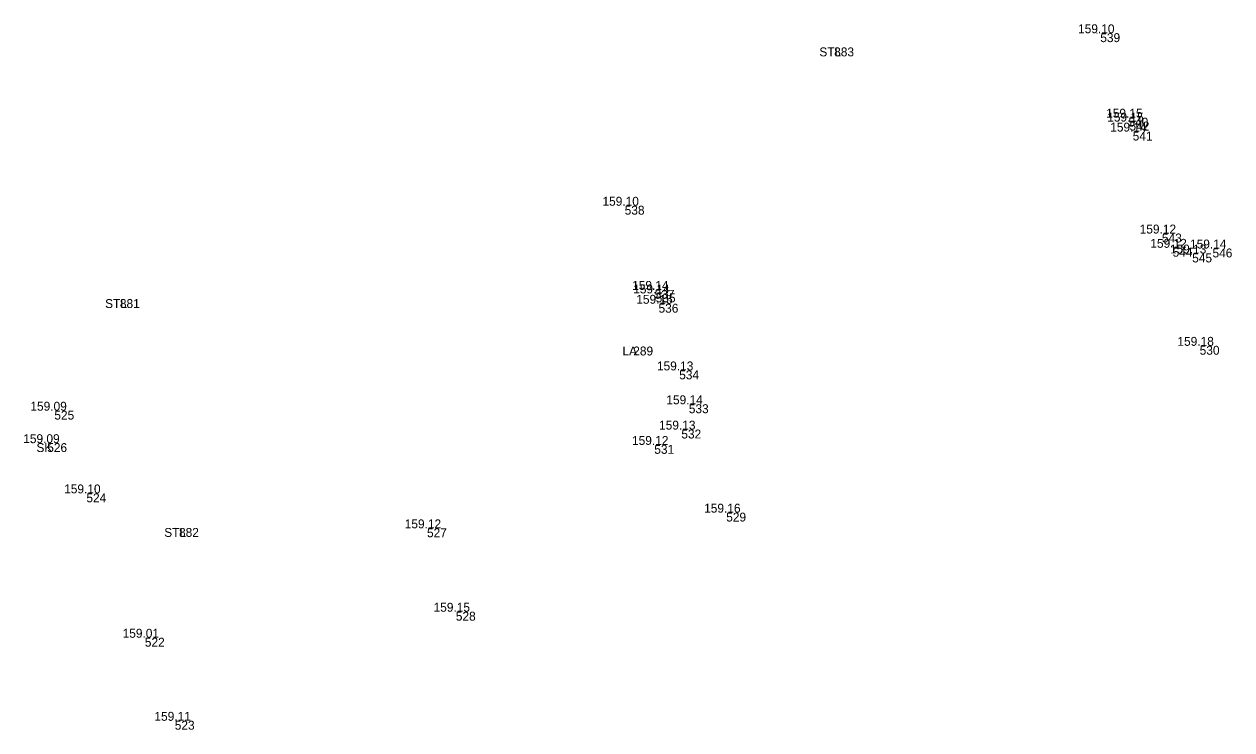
# Model space of a CAD drawing. Extents: x -583198 to -582878, y -1211024 to -1210637.
# Drawn here: x -583031.76 to -582997.86, y -1210873.42 to -1210853.63 of the extents above; entities that cross this region are included whole.
import ezdxf

# ---------------------------------------------------------------- set-up
doc = ezdxf.new("R2010")
doc.units = 0
for name, color, linetype in [('1   Kódy', 7, 'Continuous'), ('4   Body podrobné', 7, 'Continuous'), ('5   Body podrobné - čísla', 7, 'Continuous'), ('6   Body podrobné - výšky', 7, 'Continuous')]:
    doc.layers.add(name, color=color, linetype=linetype)

msp = doc.modelspace()

# ---------------------------------------------------------------- linework, layer by layer
at = {"layer": '4   Body podrobné'}
for p, q in [((-583001.65, -1210853.88), (-583001.649, -1210853.88)), ((-583009.12, -1210854.28), (-583009.119, -1210854.28)), ((-583000.86, -1210856.25), (-583000.859, -1210856.25)), ((-583000.83, -1210856.36), (-583000.829, -1210856.36)), ((-583000.74, -1210856.64), (-583000.739, -1210856.64)), ((-583015, -1210858.72), (-583014.999, -1210858.72)), ((-582999.92, -1210859.5), (-582999.919, -1210859.5)), ((-582999.62, -1210859.9), (-582999.619, -1210859.9)), ((-582999.07, -1210860.06), (-582999.069, -1210860.06)), ((-582998.5, -1210859.92), (-582998.499, -1210859.92)), ((-583014.16, -1210861.08), (-583014.159, -1210861.08)), ((-583014.13, -1210861.18), (-583014.129, -1210861.18)), ((-583029.17, -1210861.34), (-583029.169, -1210861.34)), ((-583014.05, -1210861.47), (-583014.049, -1210861.47)), ((-583014.76, -1210862.67), (-583014.759, -1210862.67)), ((-582998.86, -1210862.65), (-582998.859, -1210862.65)), ((-583013.47, -1210863.34), (-583013.469, -1210863.34)), ((-583013.2, -1210864.29), (-583013.199, -1210864.29)), ((-583031.01, -1210864.47), (-583031.009, -1210864.47)), ((-583013.41, -1210865), (-583013.409, -1210865)), ((-583031.21, -1210865.38), (-583031.209, -1210865.38)), ((-583014.17, -1210865.43), (-583014.169, -1210865.43)), ((-583030.11, -1210866.79), (-583030.109, -1210866.79)), ((-583012.15, -1210867.33), (-583012.149, -1210867.33)), ((-583027.51, -1210867.76), (-583027.509, -1210867.76)), ((-583020.55, -1210867.77), (-583020.549, -1210867.77)), ((-583019.74, -1210870.11), (-583019.739, -1210870.11)), ((-583028.47, -1210870.84), (-583028.469, -1210870.84)), ((-583027.63, -1210873.17), (-583027.629, -1210873.17))]:
    msp.add_line(p, q, dxfattribs=at)

# ---------------------------------------------------------------- texts
at = {"layer": '1   Kódy'}
for s, p in [('STL', (-583009.442, -1210854.53)), ('STL', (-583029.492, -1210861.59)), ('LA', (-583014.97, -1210862.92)), ('SK', (-583031.419, -1210865.63)), ('STL', (-583027.832, -1210868.01))]:
    msp.add_text(s, height=0.25, dxfattribs=at).set_placement(p)
at = {"layer": '5   Body podrobné - čísla'}
for s, p in [(' 539', (-583001.65, -1210854.13)), (' 883', (-583009.12, -1210854.53)), (' 540', (-583000.86, -1210856.5)), (' 542', (-583000.83, -1210856.61)), (' 541', (-583000.74, -1210856.89)), (' 538', (-583015, -1210858.97)), (' 543', (-582999.92, -1210859.75)), (' 544', (-582999.62, -1210860.15)), (' 545', (-582999.07, -1210860.31)), (' 546', (-582998.5, -1210860.17)), (' 537', (-583014.16, -1210861.33)), (' 535', (-583014.13, -1210861.43)), (' 881', (-583029.17, -1210861.59)), (' 536', (-583014.05, -1210861.72)), (' 289', (-583014.76, -1210862.92)), (' 530', (-582998.86, -1210862.9)), (' 534', (-583013.47, -1210863.59)), (' 533', (-583013.2, -1210864.54)), (' 525', (-583031.01, -1210864.72)), (' 532', (-583013.41, -1210865.25)), (' 526', (-583031.21, -1210865.63)), (' 531', (-583014.17, -1210865.68)), (' 524', (-583030.11, -1210867.04)), (' 529', (-583012.15, -1210867.58)), (' 882', (-583027.51, -1210868.01)), (' 527', (-583020.55, -1210868.02)), (' 528', (-583019.74, -1210870.36)), (' 522', (-583028.47, -1210871.09)), (' 523', (-583027.63, -1210873.42))]:
    msp.add_text(s, height=0.25, dxfattribs=at).set_placement(p)
at = {"layer": '6   Body podrobné - výšky'}
for s, p in [('159.10', (-583002.181, -1210853.88)), ('159.15', (-583001.392, -1210856.25)), ('159.15', (-583001.362, -1210856.36)), ('159.14', (-583001.278, -1210856.64)), ('159.10', (-583015.531, -1210858.72)), ('159.12', (-583000.452, -1210859.5)), ('159.12', (-583000.152, -1210859.9)), ('159.13', (-582999.602, -1210860.06)), ('159.14', (-582999.038, -1210859.92)), ('159.14', (-583014.698, -1210861.08)), ('159.14', (-583014.668, -1210861.18)), ('159.15', (-583014.582, -1210861.47)), ('159.18', (-582999.392, -1210862.65)), ('159.13', (-583014.002, -1210863.34)), ('159.09', (-583031.59, -1210864.47)), ('159.14', (-583013.738, -1210864.29)), ('159.13', (-583013.942, -1210865)), ('159.09', (-583031.79, -1210865.38)), ('159.12', (-583014.702, -1210865.43)), ('159.10', (-583030.641, -1210866.79)), ('159.16', (-583012.677, -1210867.33)), ('159.12', (-583021.082, -1210867.77)), ('159.15', (-583020.272, -1210870.11)), ('159.01', (-583029.001, -1210870.84)), ('159.11', (-583028.108, -1210873.17))]:
    msp.add_text(s, height=0.25, dxfattribs=at).set_placement(p)

doc.saveas('drawing.dxf')
